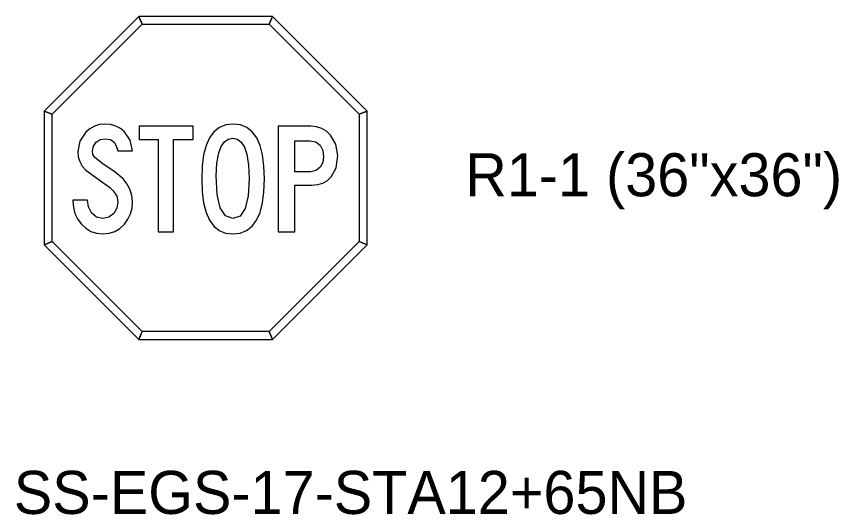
# Model space of a CAD drawing. Extents: x 620856.8 to 620948.6, y 415598.8 to 415658.2.
# Drawn here: x 620887.12 to 620894.75, y 415625.41 to 415630.03 of the extents above; entities that cross this region are included whole.
import ezdxf

# ---------------------------------------------------------------- set-up
doc = ezdxf.new("R2010")
doc.units = 0
doc.layers.add('SIGNS', color=7, linetype='Continuous')

msp = doc.modelspace()

# ---------------------------------------------------------------- linework, layer by layer
at = {"layer": 'SIGNS'}
for points in [[(620888.2526, 415630.0324), (620887.3739, 415629.1537), (620887.4469, 415629.1235), (620888.2828, 415629.9595), (620888.2526, 415630.0324), (620888.2526, 415630.0324)], [(620889.4953, 415630.0324), (620888.2526, 415630.0324), (620888.2828, 415629.9595), (620889.4651, 415629.9595), (620889.4953, 415630.0324), (620889.4953, 415630.0324)], [(620890.3739, 415629.1537), (620889.4953, 415630.0324), (620889.4651, 415629.9595), (620890.301, 415629.1235), (620890.3739, 415629.1537), (620890.3739, 415629.1537)], [(620887.3739, 415629.1537), (620887.3739, 415627.9111), (620887.4469, 415627.9413), (620887.4469, 415629.1235), (620887.3739, 415629.1537), (620887.3739, 415629.1537)], [(620890.3739, 415627.9111), (620890.3739, 415629.1537), (620890.301, 415629.1235), (620890.301, 415627.9413), (620890.3739, 415627.9111), (620890.3739, 415627.9111)], [(620887.6409, 415628.3271), (620887.6409, 415628.3181), (620887.6451, 415628.2584), (620887.6593, 415628.2031), (620887.6833, 415628.1523), (620887.7169, 415628.106), (620887.7592, 415628.0651), (620887.8073, 415628.0363), (620887.8602, 415628.019), (620887.9188, 415628.0133), (620887.9771, 415628.0186), (620888.0303, 415628.0357), (620888.0775, 415628.0637), (620888.1196, 415628.1032), (620888.1523, 415628.1486), (620888.1757, 415628.1988), (620888.1899, 415628.2533), (620888.1947, 415628.3127), (620888.1889, 415628.3695), (620888.1724, 415628.4235), (620888.1449, 415628.4747), (620888.1066, 415628.523), (620888.0327, 415628.5868), (620887.9188, 415628.6649), (620887.8435, 415628.7214), (620887.8272, 415628.75), (620887.8217, 415628.7827), (620887.8305, 415628.8265), (620887.8569, 415628.8635), (620887.8951, 415628.8884), (620887.9405, 415628.8968), (620887.9891, 415628.8888), (620888.0246, 415628.8653), (620888.0438, 415628.832), (620888.0583, 415628.7829), (620888.1947, 415628.7829), (620888.1724, 415628.883), (620888.1204, 415628.9618), (620888.0824, 415628.9924), (620888.0394, 415629.0146), (620887.9903, 415629.0279), (620887.9366, 415629.0324), (620887.8867, 415629.0275), (620887.8407, 415629.0134), (620887.798, 415628.9897), (620887.7596, 415628.9566), (620887.7037, 415628.8743), (620887.6854, 415628.7788), (620887.6899, 415628.7295), (620887.7039, 415628.6844), (620887.7274, 415628.6427), (620887.7605, 415628.6048), (620887.9198, 415628.4909), (620887.979, 415628.4459), (620888.0156, 415628.4124), (620888.048, 415628.3635), (620888.0592, 415628.3112), (620888.0495, 415628.2533), (620888.0216, 415628.2039), (620887.9753, 415628.1679), (620887.9188, 415628.1558), (620887.8585, 415628.1692), (620887.8118, 415628.2093), (620887.7845, 415628.2629), (620887.7764, 415628.3271)], [(620888.434, 415628.0324), (620888.5764, 415628.0324), (620888.5764, 415628.89), (620888.7593, 415628.89), (620888.7593, 415629.0131), (620888.2549, 415629.0131), (620888.2549, 415628.89), (620888.434, 415628.89)], [(620887.3739, 415627.9111), (620888.2526, 415627.0324), (620888.2828, 415627.1054), (620887.4469, 415627.9413), (620887.3739, 415627.9111), (620887.3739, 415627.9111)], [(620889.4953, 415627.0324), (620890.3739, 415627.9111), (620890.301, 415627.9413), (620889.4651, 415627.1054), (620889.4953, 415627.0324), (620889.4953, 415627.0324)], [(620888.2526, 415627.0324), (620889.4953, 415627.0324), (620889.4651, 415627.1054), (620888.2828, 415627.1054), (620888.2526, 415627.0324), (620888.2526, 415627.0324)]]:
    msp.add_lwpolyline(points, close=True, dxfattribs=at)
for points in [[(620889.4204, 415628.5243), (620889.4156, 415628.6429), (620889.4021, 415628.7463), (620889.3795, 415628.8335), (620889.348, 415628.9052), (620889.3068, 415628.9605), (620889.2572, 415629.0006), (620889.1984, 415629.0243), (620889.1308, 415629.0324), (620889.0617, 415629.0243), (620889.0019, 415629.0006), (620888.9513, 415628.9605), (620888.9102, 415628.9052), (620888.8781, 415628.8335), (620888.8553, 415628.7463), (620888.8413, 415628.6429), (620888.8369, 415628.5243), (620888.8411, 415628.404), (620888.8546, 415628.3004), (620888.8771, 415628.2124), (620888.9087, 415628.1408), (620888.949, 415628.0847), (620888.9986, 415628.045), (620889.0572, 415628.0211), (620889.1248, 415628.0133), (620889.1939, 415628.0211), (620889.2539, 415628.045), (620889.3047, 415628.0847), (620889.3465, 415628.1408), (620889.3787, 415628.2124), (620889.4018, 415628.3004), (620889.4156, 415628.404), (620889.4204, 415628.5243)], [(620889.8494, 415629.0131), (620889.5469, 415629.0131), (620889.5469, 415628.0324), (620889.7007, 415628.0324), (620889.7007, 415628.4657), (620889.856, 415628.4657), (620889.9129, 415628.4704), (620889.9627, 415628.4849), (620890.0054, 415628.509), (620890.0412, 415628.5426), (620890.0856, 415628.6276), (620890.1007, 415628.7395), (620890.0838, 415628.8449), (620890.0342, 415628.9314), (620889.9962, 415628.9671), (620889.9526, 415628.9928), (620889.9035, 415629.008), (620889.8494, 415629.0131)], [(620889.2792, 415628.5288), (620889.2696, 415628.3653), (620889.2408, 415628.249), (620889.1929, 415628.179), (620889.1262, 415628.1558), (620889.0584, 415628.1805), (620889.0099, 415628.2551), (620888.9811, 415628.3791), (620888.9715, 415628.5534), (620888.9776, 415628.6692), (620888.9961, 415628.7652), (620889.0183, 415628.8242), (620889.0475, 415628.8668), (620889.0833, 415628.8921), (620889.1262, 415628.9007), (620889.1684, 415628.8914), (620889.2041, 415628.8635), (620889.2332, 415628.817), (620889.2558, 415628.7523), (620889.2732, 415628.6505), (620889.2792, 415628.5288)], [(620889.8519, 415628.59), (620889.7007, 415628.59), (620889.7007, 415628.8785), (620889.8422, 415628.8785), (620889.8975, 415628.8678), (620889.9378, 415628.8361), (620889.9619, 415628.788), (620889.9699, 415628.7282), (620889.9621, 415628.6751), (620889.9387, 415628.6318), (620889.9008, 415628.6003), (620889.8519, 415628.59)]]:
    msp.add_lwpolyline(points, dxfattribs=at)

# ---------------------------------------------------------------- texts
for s, p in [('R1-1 (36"x36")', (620891.2851, 415628.3623)), ('SS-EGS-17-STA12+65NB', (620887.0917, 415625.4121))]:
    msp.add_text(s, height=0.4, rotation=0, dxfattribs=at).set_placement(p)

doc.saveas('drawing.dxf')
